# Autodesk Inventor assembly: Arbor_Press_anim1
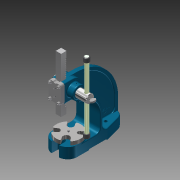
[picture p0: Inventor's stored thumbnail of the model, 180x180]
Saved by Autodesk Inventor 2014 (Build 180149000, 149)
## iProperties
Shininess: 64.0
Length Units: 11272
Angle Units: 11279
Time Units: 11290
Mass Units: 11286
Length Display Precision: 3
Angle Display Precision: 2
Compacted: True
Part Number: Arbor_Press_anim1
Document SubType Name: Assembly
Created: 2003-11
Designer: Autodesk, Inc
Manufacturer: Standard
Standards Organization: Custom
Mass: 8057.89 g
Surface Area: 2435.26 cm^2
Volume: 1030.81 cm^3
Density: 7.81702 g/cm^3
Density: 0.0
Volumn: 0.0
Area: 0.0
PropertySet Name: Model Information
Control State: 0
Master: False
Checked Out: False
Title: Arbor Press
Author: Autodesk, Inc
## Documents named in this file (15)
- C:\Users\iTools\Desktop\tutorial files\Arbor Press\Arbor_Press_anim1.iam
- C:\Users\iTools\Desktop\tutorial files\Arbor Press\Components\Arbor_Frame.ipt
- C:\Users\iTools\Desktop\tutorial files\Arbor Press\Components\COLLAR.ipt
- C:\Users\iTools\Desktop\tutorial files\Arbor Press\Components\PINION SHAFT.ipt
- C:\Users\iTools\Desktop\tutorial files\Arbor Press\Components\LEVER ARM.ipt
- C:\Users\iTools\Desktop\tutorial files\Arbor Press\Components\THUMB SCREW.ipt
- C:\Users\iTools\Desktop\tutorial files\Arbor Press\Components\GIB PLATE.ipt
- C:\Users\iTools\Desktop\tutorial files\Arbor Press\Components\GROOVE PIN.ipt
- C:\Users\iTools\Desktop\tutorial files\Arbor Press\Components\TABLE PLATE.ipt
- C:\Users\iTools\Desktop\tutorial files\Arbor Press\Components\RAM.ipt
- C:\Users\iTools\Desktop\tutorial files\Arbor Press\Components\HANDLE CAP.ipt
- C:\Users\iTools\Desktop\tutorial files\Arbor Press\Components\FACE PLATE.ipt
- C:\Users\iTools\Desktop\tutorial files\Arbor Press\Standard Parts\ANSI B18.3 - 1_4-20 UNC - 0.875(31).ipt
- C:\Users\iTools\Desktop\tutorial files\Arbor Press\Standard Parts\ISO 4026 - M5 x 16ISO.ipt
- C:\Users\iTools\Desktop\tutorial files\Arbor Press\Standard Parts\ISO 4766 - M5 x 5ISO.ipt
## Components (21 placed, 14 different names)
1. Arbor_Frame:1 — Mate:1, Insert:3, Insert:6, Insert:7, Angle SHAFT TURN, Angle PLATE, Flush:7, Mate:14, Flush:11, Flush:12, Mate:15, Flush:13, Flush:23, Flush:24
2. FACE PLATE:1 — Flush:2, Mate:14, Flush:9, Flush:10, Flush:12, Flush:23, Flush:24
3. PINION SHAFT:1 — Mate:3, Insert:7, Rotation/Translation:1, Angle SHAFT TURN, Mate:12, Insert:12, Mate:17
4. LEVER ARM:1 — Mate:3, Mate:12
5. THUMB SCREW:1 — Insert:12, Mate:17
6. TABLE PLATE:1 — Insert:3, Mate:5, Angle PLATE, Mate HEIGHT
7. RAM:1 — Mate:1, Rotation/Translation:1, Flush:11, Mate HEIGHT
8. HANDLE CAP:1
9. HANDLE CAP:2
10. COLLAR:1 — Insert:6, Mate:30, Tangent:1
11. GIB PLATE:1 — Flush:2, Flush:9, Flush:10
12. GROOVE PIN:1 — Mate:5, Flush:7
13. Hexagon Socket Head Cap Screw - Inch 1/4 - 20 UNC - 7/8:1
14. Hexagon Socket Head Cap Screw - Inch 1/4 - 20 UNC - 7/8:2
15. Hexagon Socket Head Cap Screw - Inch 1/4 - 20 UNC - 7/8:3
16. Hexagon Socket Head Cap Screw - Inch 1/4 - 20 UNC - 7/8:4
17. ISO 4026 M5 x 16:1
18. ISO 4026 M5 x 16:2
19. ISO 4026 M5 x 16:3
20. ISO 4026 M5 x 16:4
21. ISO 4766 M5 x 5:1 — Mate:30, Tangent:1
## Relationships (26: Mate 9, Flush 9, Insert 4, Angle 2, RelateRotateTranslate 1, Tangent 1)
- Mate:1: Arbor_Frame:1 ↔ RAM:1
- Insert:3: Arbor_Frame:1 ↔ TABLE PLATE:1
- Mate:3: PINION SHAFT:1 ↔ LEVER ARM:1
- Insert:6: Arbor_Frame:1 ↔ COLLAR:1
- Mate:5: TABLE PLATE:1 ↔ GROOVE PIN:1
- Insert:7: Arbor_Frame:1 ↔ PINION SHAFT:1
- Flush:2: FACE PLATE:1 ↔ GIB PLATE:1
- Rotation/Translation:1 [RelateRotateTranslate]: PINION SHAFT:1 ↔ RAM:1
- Angle SHAFT TURN: Arbor_Frame:1 ↔ PINION SHAFT:1
- Angle PLATE: Arbor_Frame:1 ↔ TABLE PLATE:1
- Mate:12: PINION SHAFT:1 ↔ LEVER ARM:1
- Flush:7: Arbor_Frame:1 ↔ GROOVE PIN:1
- Mate:14: Arbor_Frame:1 ↔ FACE PLATE:1
- Flush:9: FACE PLATE:1 ↔ GIB PLATE:1
- Flush:10: FACE PLATE:1 ↔ GIB PLATE:1
- Flush:11: Arbor_Frame:1 ↔ RAM:1
- Flush:12: Arbor_Frame:1 ↔ FACE PLATE:1
- Mate:15: Arbor_Frame:1
- Flush:13: Arbor_Frame:1
- Insert:12: PINION SHAFT:1 ↔ THUMB SCREW:1
- Mate:17: PINION SHAFT:1 ↔ THUMB SCREW:1
- Flush:23: Arbor_Frame:1 ↔ FACE PLATE:1
- Flush:24: Arbor_Frame:1 ↔ FACE PLATE:1
- Mate HEIGHT: TABLE PLATE:1 ↔ RAM:1
- Mate:30: COLLAR:1 ↔ ISO 4766 M5 x 5:1
- Tangent:1: COLLAR:1 ↔ ISO 4766 M5 x 5:1
